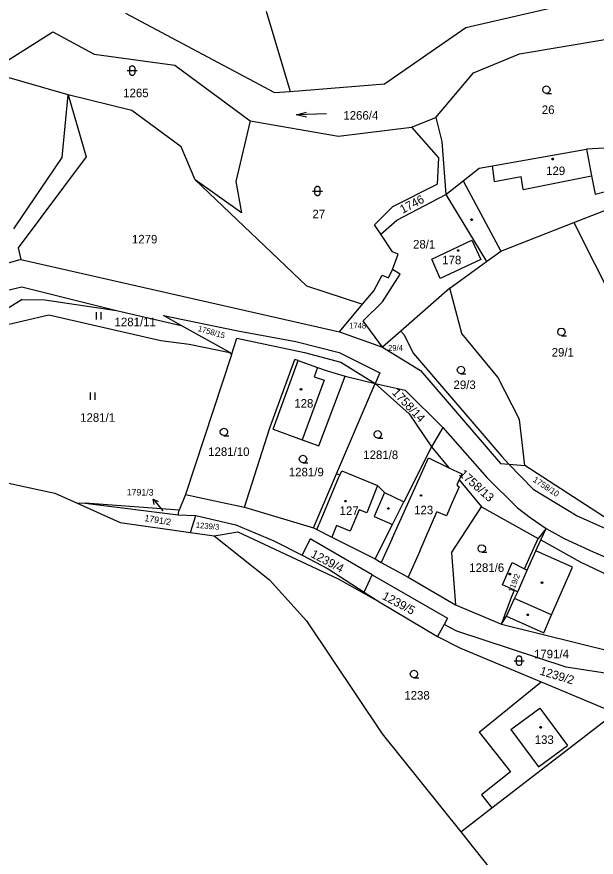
# Model space of a CAD drawing. Extents: x -799786 to -795190, y -1021716 to -1017834.
# Drawn here: x -798278.5 to -798163.2, y -1019191.9 to -1019024.7 of the extents above; entities that cross this region are included whole.
import ezdxf

# ---------------------------------------------------------------- set-up
doc = ezdxf.new("R2010")
doc.units = 0
for name, color, linetype in [('Default', 7, 'Continuous'), ('KN_HRANICE', 7, 'Continuous'), ('KN_KULTURY', 7, 'Continuous'), ('KN_PARCELY', 7, 'Continuous'), ('KN_SLUCKY', 7, 'Continuous')]:
    doc.layers.add(name, color=color, linetype=linetype)

# ---------------------------------------------------------------- blocks, each defined once
blk = doc.blocks.new('304')
at = {"layer": 'Default'}
blk.add_lwpolyline([(0, 0), (-0.38, 0.1), (-0.65, 0.37), (-0.75, 0.74), (-0.65, 1.11), (-0.38, 1.38), (-0.01, 1.48), (0.36, 1.38), (0.63, 1.11), (0.73, 0.73), (0.63, 0.35), (0.36, 0.08), (-0.02, -0.02), (0.98, -0.02)], dxfattribs=at)
blk = doc.blocks.new('306')
at = {"layer": 'Default'}
for p, q in [((-0.5, 1.5), (-0.5, 0)), ((0.5, 0), (0.5, 1.5))]:
    blk.add_line(p, q, dxfattribs=at)
blk = doc.blocks.new('316')
at = {"layer": 'Default'}
for points in [[(-0.5, 1.5), (-0.4, 1.79), (-0.15, 1.97), (0.16, 1.97), (0.41, 1.79), (0.51, 1.5), (0.51, 0.5), (0.41, 0.21), (0.16, 0.03), (-0.15, 0.03), (-0.4, 0.21), (-0.5, 0.5), (-0.5, 1.5)], [(-1, 1), (0.27, 1), (1, 1)]]:
    blk.add_lwpolyline(points, dxfattribs=at)
blk = doc.blocks.new('802')
at = {"layer": 'Default'}
blk.add_line((-3, 0), (3, 0), dxfattribs=at)
blk.add_lwpolyline([(1, 0.5), (3, 0), (1, -0.5)], dxfattribs=at)
blk = doc.blocks.new('10292')
at = {"layer": 'Default'}
blk.add_line((0, 3), (0, 0), dxfattribs=at)
blk.add_lwpolyline([(-0.5, 2), (0, 3), (0.5, 2)], dxfattribs=at)
blk = doc.blocks.new('402')
at = {"layer": 'Default'}
blk.add_lwpolyline([(0.09, 0.15), (0.18, 0), (0.09, -0.15), (-0.09, -0.15), (-0.18, 0), (-0.09, 0.15), (0.09, 0.15)], dxfattribs=at)

msp = doc.modelspace()

# ---------------------------------------------------------------- linework, layer by layer
at = {"layer": 'KN_HRANICE'}
for p, q in [((-798189.16, -1019026.83), (-798161.85, -1019020.48)), ((-798256.91, -1019023.98), (-798227.2, -1019039.74)), ((-798228.9, -1019023.55), (-798224.09, -1019039.53)), ((-798284.03, -1019035.68), (-798271.37, -1019027.66)), ((-798271.37, -1019027.66), (-798263.11, -1019032.14)), ((-798205.34, -1019038), (-798189.16, -1019026.83)), ((-798178.49, -1019032.04), (-798161.12, -1019029.12)), ((-798263.11, -1019032.14), (-798247.1, -1019034.33)), ((-798187.61, -1019035.85), (-798178.49, -1019032.04)), ((-798247.1, -1019034.33), (-798232.07, -1019045.38)), ((-798268.28, -1019040.2), (-798284.03, -1019035.68)), ((-798195.12, -1019044.71), (-798187.61, -1019035.85)), ((-798227.2, -1019039.74), (-798224.09, -1019039.53)), ((-798224.09, -1019039.53), (-798205.34, -1019038)), ((-798269.48, -1019052.64), (-798268.28, -1019040.2)), ((-798255.65, -1019043.29), (-798268.28, -1019040.2)), ((-798268.28, -1019040.2), (-798264.7, -1019052.54)), ((-798245.8, -1019050.55), (-798255.65, -1019043.29)), ((-798232.07, -1019045.38), (-798234.96, -1019057.42)), ((-798232.07, -1019045.38), (-798214.47, -1019048.4)), ((-798199.94, -1019046.65), (-798195.12, -1019044.71)), ((-798195.12, -1019044.71), (-798193.95, -1019049.51)), ((-798214.47, -1019048.4), (-798199.94, -1019046.65)), ((-798199.94, -1019046.65), (-798194.61, -1019052.72)), ((-798193.95, -1019049.51), (-798193.16, -1019060.03)), ((-798243.02, -1019057.12), (-798245.8, -1019050.55)), ((-798183.88, -1019054.32), (-798165.14, -1019051)), ((-798157.02, -1019050.59), (-798165.14, -1019051)), ((-798165.14, -1019051), (-798164.12, -1019056.34)), ((-798279.13, -1019066.87), (-798269.48, -1019052.64)), ((-798264.7, -1019052.54), (-798278.23, -1019070.65)), ((-798194.61, -1019052.72), (-798194.84, -1019057.97)), ((-798186.5, -1019054.79), (-798183.88, -1019054.32)), ((-798189.68, -1019057.3), (-798186.5, -1019054.79)), ((-798163.44, -1019059.94), (-798148.3, -1019056.22)), ((-798233.77, -1019063.69), (-798243.02, -1019057.12)), ((-798243.02, -1019057.12), (-798220.85, -1019078.22)), ((-798234.96, -1019057.42), (-798233.77, -1019063.69)), ((-798193.16, -1019060.03), (-798189.68, -1019057.3)), ((-798167.64, -1019065.62), (-798146.66, -1019057.36)), ((-798164.12, -1019056.34), (-798163.44, -1019059.94)), ((-798203.7, -1019062.43), (-798194.84, -1019057.97)), ((-798202.86, -1019065.12), (-798193.16, -1019060.03)), ((-798193.16, -1019060.03), (-798185.02, -1019073.35)), ((-798207.32, -1019066.09), (-798203.7, -1019062.43)), ((-798206.08, -1019067.93), (-798207.32, -1019066.09)), ((-798206.08, -1019067.93), (-798202.86, -1019065.12)), ((-798182.19, -1019071.31), (-798167.64, -1019065.62)), ((-798167.64, -1019065.62), (-798151.06, -1019098.77)), ((-798203.74, -1019071.47), (-798206.08, -1019067.93)), ((-798278.23, -1019070.65), (-798277.73, -1019072.94)), ((-798185.02, -1019073.35), (-798182.19, -1019071.31)), ((-798277.73, -1019072.94), (-798294.15, -1019077.72)), ((-798277.73, -1019072.94), (-798214.27, -1019087.39)), ((-798202.62, -1019071.89), (-798203.74, -1019071.47)), ((-798203.72, -1019074.94), (-798202.62, -1019071.89)), ((-798192.35, -1019078.65), (-798185.02, -1019073.35)), ((-798207.48, -1019079.22), (-798205.8, -1019076.09)), ((-798205.8, -1019076.09), (-798204.52, -1019076.62)), ((-798205.73, -1019081.39), (-798202.2, -1019075.87)), ((-798204.52, -1019076.62), (-798203.72, -1019074.94)), ((-798202.2, -1019075.87), (-798203.72, -1019074.94)), ((-798292.31, -1019081.83), (-798277.52, -1019078.42)), ((-798277.52, -1019078.42), (-798258.67, -1019083.12)), ((-798220.85, -1019078.22), (-798209.69, -1019081.83)), ((-798209.69, -1019081.83), (-798207.48, -1019079.22)), ((-798192.35, -1019078.65), (-798202.12, -1019087.23)), ((-798189.97, -1019087.69), (-798192.35, -1019078.65)), ((-798277.42, -1019080.9), (-798285.9, -1019086.17)), ((-798277.42, -1019080.9), (-798272.92, -1019080.98)), ((-798272.92, -1019080.98), (-798258.67, -1019083.12)), ((-798214.27, -1019087.39), (-798209.69, -1019081.83)), ((-798209.57, -1019085.19), (-798205.73, -1019081.39)), ((-798283.51, -1019086.63), (-798272.14, -1019083.99)), ((-798272.14, -1019083.99), (-798249.85, -1019089.07)), ((-798258.67, -1019083.12), (-798245.78, -1019086.08)), ((-798236.1, -1019091.47), (-798245.78, -1019086.08)), ((-798205.73, -1019090.39), (-798209.57, -1019085.19)), ((-798214.27, -1019087.39), (-798205.73, -1019090.39)), ((-798202.12, -1019087.23), (-798205.73, -1019090.39)), ((-798182.82, -1019096.35), (-798189.97, -1019087.69)), ((-798249.85, -1019089.07), (-798244.19, -1019089.84)), ((-798235.78, -1019091.93), (-798234.73, -1019088.61)), ((-798234.73, -1019088.61), (-798221.24, -1019091.45)), ((-798244.19, -1019089.84), (-798236.1, -1019091.47)), ((-798205.73, -1019090.39), (-798198.18, -1019095.03)), ((-798235.78, -1019091.93), (-798244.94, -1019119.72)), ((-798236.1, -1019091.47), (-798235.78, -1019091.93)), ((-798228.16, -1019106.48), (-798223.16, -1019092.85)), ((-798222.5, -1019093.08), (-798223.16, -1019092.85)), ((-798221.24, -1019091.45), (-798214.02, -1019093.39)), ((-798227.51, -1019106.73), (-798222.5, -1019093.08)), ((-798222.5, -1019093.08), (-798218.69, -1019094.45)), ((-798218.69, -1019094.45), (-798216.78, -1019095.14)), ((-798214.02, -1019093.39), (-798207.19, -1019097.64)), ((-798218.4, -1019110.04), (-798213.18, -1019096.15)), ((-798216.78, -1019095.14), (-798213.18, -1019096.15)), ((-798213.18, -1019096.15), (-798207.19, -1019097.64)), ((-798198.18, -1019095.03), (-798182.29, -1019113.53)), ((-798178.45, -1019104.78), (-798182.82, -1019096.35)), ((-798214.89, -1019115.61), (-798207.19, -1019097.64)), ((-798207.19, -1019097.64), (-798200.43, -1019103.69)), ((-798200.43, -1019103.69), (-798195.98, -1019110.26)), ((-798193.73, -1019106.42), (-798195.98, -1019110.26)), ((-798177.44, -1019113.97), (-798178.45, -1019104.78)), ((-798233.18, -1019122.25), (-798228.16, -1019106.48)), ((-798227.51, -1019106.73), (-798221.72, -1019108.83)), ((-798221.72, -1019108.83), (-798218.4, -1019110.04)), ((-798195.98, -1019110.26), (-798201.47, -1019121.22)), ((-798195.98, -1019110.26), (-798192.54, -1019114.39)), ((-798182.29, -1019113.53), (-798180.57, -1019113.69)), ((-798180.57, -1019113.69), (-798177.44, -1019113.97)), ((-798158.15, -1019126.49), (-798177.44, -1019113.97)), ((-798219.5, -1019126.38), (-798214.89, -1019115.61)), ((-798214.24, -1019115.88), (-798214.89, -1019115.61)), ((-798281.71, -1019117.15), (-798270.95, -1019119.48)), ((-798206.71, -1019117.93), (-798205.33, -1019119.33)), ((-798190.5, -1019116.82), (-798186.04, -1019122.17)), ((-798270.95, -1019119.48), (-798266.63, -1019121.42)), ((-798244.94, -1019119.72), (-798246.22, -1019122.85)), ((-798244.94, -1019119.72), (-798237.56, -1019121.31)), ((-798205.33, -1019119.33), (-798201.47, -1019121.22)), ((-798266.63, -1019121.42), (-798257.97, -1019125.3)), ((-798266.63, -1019121.42), (-798264.91, -1019121.48)), ((-798246.22, -1019122.85), (-798264.91, -1019121.48)), ((-798264.91, -1019121.48), (-798246.43, -1019123.75)), ((-798237.56, -1019121.31), (-798233.18, -1019122.25)), ((-798203.76, -1019125.7), (-798201.47, -1019121.22)), ((-798246.43, -1019123.75), (-798246.22, -1019122.85)), ((-798233.18, -1019122.25), (-798219.5, -1019126.38)), ((-798192, -1019131.32), (-798186.04, -1019122.17)), ((-798186.04, -1019122.17), (-798174.76, -1019128.46)), ((-798246.43, -1019123.75), (-798242.91, -1019123.9)), ((-798243.97, -1019127.3), (-798242.91, -1019123.9)), ((-798242.91, -1019123.9), (-798234.96, -1019125.77)), ((-798257.97, -1019125.3), (-798243.97, -1019127.3)), ((-798234.96, -1019125.77), (-798227.36, -1019128.96)), ((-798219.5, -1019126.38), (-798218.83, -1019126.71)), ((-798207.23, -1019132.5), (-798203.76, -1019125.7)), ((-798173.18, -1019126.48), (-798174.76, -1019128.46)), ((-798174.26, -1019128.74), (-798173.18, -1019126.48)), ((-798243.97, -1019127.3), (-798239.23, -1019127.98)), ((-798239.23, -1019127.98), (-798234.52, -1019127.16)), ((-798239.23, -1019127.98), (-798228.23, -1019136.68)), ((-798234.52, -1019127.16), (-798214.54, -1019136.48)), ((-798218.83, -1019126.71), (-798215.85, -1019128.2)), ((-798227.36, -1019128.96), (-798221.75, -1019131.83)), ((-798220.12, -1019128.55), (-798221.75, -1019131.83)), ((-798207.8, -1019135.71), (-798220.12, -1019128.55)), ((-798215.85, -1019128.2), (-798207.23, -1019132.5)), ((-798175.73, -1019130.68), (-798174.76, -1019128.46)), ((-798175.25, -1019130.94), (-798174.26, -1019128.74)), ((-798174.26, -1019128.74), (-798166.41, -1019133.11)), ((-798192, -1019131.32), (-798191.24, -1019141.68)), ((-798177.5, -1019134.51), (-798175.73, -1019130.68)), ((-798176.95, -1019134.79), (-798175.25, -1019130.94)), ((-798207.23, -1019132.5), (-798205.98, -1019133.26)), ((-798166.41, -1019133.11), (-798156.68, -1019137.76)), ((-798205.98, -1019133.26), (-798200.63, -1019136.21)), ((-798178.84, -1019139.07), (-798176.95, -1019134.79)), ((-798214.54, -1019136.48), (-798206.29, -1019141.16)), ((-798209.36, -1019139.14), (-798207.8, -1019135.71)), ((-798200.63, -1019136.21), (-798191.24, -1019141.68)), ((-798228.23, -1019136.68), (-798220.84, -1019144.84)), ((-798209.36, -1019139.14), (-798206.29, -1019141.16)), ((-798180.1, -1019140.15), (-798179.47, -1019138.79)), ((-798179.48, -1019140.44), (-798178.84, -1019139.07)), ((-798206.29, -1019141.16), (-798194.81, -1019147.97)), ((-798182.05, -1019145.56), (-798180.1, -1019140.15)), ((-798181.07, -1019143.95), (-798179.48, -1019140.44)), ((-798191.24, -1019141.68), (-798182.05, -1019145.56)), ((-798220.84, -1019144.84), (-798205.83, -1019167.34)), ((-798182.05, -1019145.56), (-798181.07, -1019143.95)), ((-798193.49, -1019145.63), (-798194.81, -1019147.97)), ((-798190.98, -1019146.92), (-798193.49, -1019145.63)), ((-798182.05, -1019145.56), (-798139.27, -1019156.11)), ((-798194.81, -1019147.97), (-798190.22, -1019150.28)), ((-798169.21, -1019154.08), (-798190.98, -1019146.92)), ((-798190.22, -1019150.28), (-798174.14, -1019157.02)), ((-798140.66, -1019158.48), (-798169.21, -1019154.08)), ((-798186.49, -1019167.03), (-798174.14, -1019157.02)), ((-798174.14, -1019157.02), (-798159.42, -1019163.19)), ((-798183.97, -1019182.09), (-798159.42, -1019163.19)), ((-798205.83, -1019167.34), (-798190.13, -1019186.83)), ((-798186.49, -1019167.03), (-798180.26, -1019174.89)), ((-798180.26, -1019174.89), (-798186.02, -1019179.49)), ((-798186.02, -1019179.49), (-798183.97, -1019182.09)), ((-798190.13, -1019186.83), (-798183.97, -1019182.09)), ((-798190.13, -1019186.83), (-798182.57, -1019196.42))]:
    msp.add_line(p, q, dxfattribs=at)
msp.add_lwpolyline([(-798195.91, -1019072.93), (-798187.93, -1019069.13), (-798186.15, -1019073), (-798194.26, -1019076.74)], close=True, dxfattribs=at)
for points in [[(-798245.78, -1019086.08), (-798249.3, -1019084.11), (-798234.55, -1019087.18), (-798222.98, -1019089.3), (-798214.38, -1019091.46), (-798206.26, -1019095.51), (-798207.19, -1019097.64)], [(-798202.12, -1019087.23), (-798201.5, -1019087.88), (-798199.54, -1019091.67), (-798182.01, -1019112.18), (-798180.57, -1019113.69)], [(-798207.19, -1019097.64), (-798201.21, -1019098.97), (-798193.73, -1019106.42)], [(-798193.73, -1019106.42), (-798184.98, -1019116.32), (-798178.89, -1019122.36), (-798176.36, -1019124.29), (-798173.18, -1019126.48)], [(-798192.54, -1019114.39), (-798189.93, -1019115.64), (-798190.5, -1019116.82)], [(-798180.57, -1019113.69), (-798175.77, -1019118.66), (-798166.98, -1019124), (-798161.34, -1019126.51), (-798158.43, -1019127.29), (-798158.15, -1019126.49)], [(-798214.24, -1019115.88), (-798213.86, -1019115), (-798206.71, -1019117.93)], [(-798173.18, -1019126.48), (-798169.57, -1019128.51), (-798163.84, -1019131.17), (-798156.24, -1019134.41), (-798147.55, -1019137.5), (-798137.22, -1019139.95), (-798137.74, -1019143.13)], [(-798221.75, -1019131.83), (-798216.55, -1019134.49), (-798209.36, -1019139.14)], [(-798179.47, -1019138.79), (-798181.88, -1019137.71), (-798179.91, -1019133.27), (-798177.5, -1019134.51)], [(-798207.8, -1019135.71), (-798192.78, -1019144.36), (-798193.49, -1019145.63)]]:
    msp.add_lwpolyline(points, dxfattribs=at)
at = {"layer": 'KN_SLUCKY'}
for p, q in [((-798183.46, -1019057.46), (-798183.88, -1019054.32)), ((-798189.68, -1019057.3), (-798182.19, -1019071.31)), ((-798183.46, -1019057.46), (-798178.16, -1019056.45)), ((-798177.78, -1019059.04), (-798178.16, -1019056.45)), ((-798177.78, -1019059.04), (-798164.12, -1019056.34)), ((-798218.69, -1019094.45), (-798219.34, -1019096.34)), ((-798219.34, -1019096.34), (-798217.34, -1019096.99)), ((-798217.34, -1019096.99), (-798221.72, -1019108.83)), ((-798203.83, -1019128.48), (-798197.73, -1019114.97)), ((-798191.85, -1019121.33), (-798193.02, -1019123.97)), ((-798198.34, -1019130.99), (-798194.9, -1019123.15)), ((-798193.02, -1019123.97), (-798194.9, -1019123.15)), ((-798218.83, -1019126.71), (-798217.94, -1019124.72)), ((-798214.91, -1019125.93), (-798215.85, -1019128.2)), ((-798212.17, -1019127.02), (-798214.91, -1019125.93)), ((-798203.83, -1019128.48), (-798205.98, -1019133.26)), ((-798198.34, -1019130.99), (-798200.63, -1019136.21)), ((-798167.92, -1019134.21), (-798175.25, -1019130.94)), ((-798177.5, -1019134.51), (-798176.95, -1019134.79)), ((-798172.11, -1019143.69), (-798167.92, -1019134.21)), ((-798179.47, -1019138.79), (-798178.84, -1019139.07)), ((-798172.11, -1019143.69), (-798179.48, -1019140.44)), ((-798180.17, -1019166.51), (-798174.4, -1019162.26)), ((-798174.4, -1019162.26), (-798168.9, -1019169.7)), ((-798180.17, -1019166.51), (-798174.67, -1019173.95)), ((-798174.67, -1019173.95), (-798168.9, -1019169.7))]:
    msp.add_line(p, q, dxfattribs=at)
for points in [[(-798197.73, -1019114.97), (-798196.59, -1019112.44), (-798192.54, -1019114.39)], [(-798217.94, -1019124.72), (-798214.47, -1019116.41), (-798214.24, -1019115.88)], [(-798206.71, -1019117.93), (-798208.86, -1019123.41), (-798210.4, -1019122.79), (-798212.17, -1019127.02)], [(-798190.5, -1019116.82), (-798190.98, -1019117.82), (-798190.78, -1019118.07), (-798190.47, -1019118.22), (-798191.85, -1019121.33)], [(-798205.33, -1019119.33), (-798207.39, -1019124.11), (-798203.76, -1019125.7)], [(-798181.07, -1019143.95), (-798173.64, -1019147.25), (-798172.11, -1019143.69)]]:
    msp.add_lwpolyline(points, dxfattribs=at)

# ---------------------------------------------------------------- block references
at = {"layer": 'KN_KULTURY'}
for name, p in [('316', (-798255.55, -1019036.37)), ('304', (-798173.11, -1019039.91)), ('402', (-798171.86, -1019052.97)), ('316', (-798218.69, -1019060.34)), ('402', (-798188.01, -1019065.04)), ('402', (-798190.69, -1019071.19)), ('306', (-798262.23, -1019084.93)), ('304', (-798170.13, -1019088.11)), ('304', (-798190.12, -1019095.69)), ('306', (-798263.42, -1019100.9)), ('402', (-798221.97, -1019098.8)), ('304', (-798237.3, -1019108.02)), ('304', (-798206.67, -1019108.5)), ('304', (-798221.56, -1019113.41)), ('402', (-798198.09, -1019119.93)), ('402', (-798213.11, -1019121.07)), ('402', (-798204.59, -1019122.53)), ('304', (-798185.97, -1019131.21)), ('402', (-798174.01, -1019137.26)), ('402', (-798176.83, -1019143.66)), ('316', (-798178.56, -1019153.8)), ('304', (-798199.48, -1019156.18)), ('402', (-798174.26, -1019166.05))]:
    msp.add_blockref(name, p, dxfattribs=at)
for name, p, rotation in [('802', (-798219.87, -1019044.09), -178.37237900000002), ('402', (-798180.41, -1019135.56), -11.92813899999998)]:
    msp.add_blockref(name, p, dxfattribs=dict(at, rotation=rotation))
at = {"layer": 'KN_PARCELY', "rotation": 39.992453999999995}
msp.add_blockref('10292', (-798249.48, -1019122.95), dxfattribs=at)

# ---------------------------------------------------------------- texts
at = {"layer": 'KN_PARCELY'}
for s, height, p in [('1265', 1.7, (-798257.34, -1019040.67)), ('26', 1.7, (-798174.04, -1019044.02)), ('1266/4', 1.7, (-798213.53, -1019045.14)), ('129', 1.7, (-798173.18, -1019056.17)), ('27', 1.7, (-798219.68, -1019064.77)), ('1279', 1.7, (-798255.6, -1019069.77)), ('28/1', 1.7, (-798199.66, -1019070.78)), ('178', 1.7, (-798193.85, -1019073.92)), ('1281/11', 1.7, (-798259.06, -1019086.24)), ('1748', 1.14, (-798212.38, -1019086.69)), ('29/1', 1.7, (-798172.07, -1019092.28)), ('29/3', 1.7, (-798191.61, -1019098.75)), ('128', 1.7, (-798223.29, -1019102.44)), ('1281/1', 1.7, (-798265.91, -1019105.26)), ('1281/10', 1.7, (-798240.43, -1019112.06)), ('1281/8', 1.7, (-798209.57, -1019112.68)), ('1281/9', 1.7, (-798224.38, -1019116.11)), ('1791/3', 0.1, (-798249.78, -1019122.95)), ('127', 1.7, (-798214.28, -1019123.8)), ('123', 1.7, (-798199.44, -1019123.66)), ('1281/6', 1.7, (-798188.47, -1019135.14)), ('1791/4', 1.7, (-798175.59, -1019152.32)), ('1238', 1.7, (-798201.4, -1019160.54)), ('133', 1.7, (-798175.45, -1019169.36))]:
    msp.add_text(s, height=height, dxfattribs=at).set_placement(p)
for s, height, rotation, p in [('1746', 1.7, 27.846, (-798201.73, -1019063.88)), ('1758/15', 1.14, 344.061, (-798242.57, -1019087.19)), ('29/4', 1.14, 0.115, (-798204.64, -1019091.12)), ('1758/14', 1.7, 313.465, (-798203.96, -1019099.57)), ('1758/13', 1.7, 318.221, (-798190.63, -1019115.84)), ('1758/10', 1.2, 326.529, (-798175.92, -1019117.08)), ('1791/3', 1.3, 359.588, (-798256.63, -1019119.91)), ('1791/2', 1.3, 350.421, (-798253.18, -1019125.01)), ('1239/3', 1.14, 354.833, (-798242.92, -1019126.36)), ('1239/4', 1.7, 331.972, (-798220.16, -1019132.09)), ('119/2', 1.14, 68.64, (-798179.72, -1019139.33)), ('1239/5', 1.7, 331.857, (-798205.97, -1019140.44)), ('1239/2', 1.7, 343.259, (-798174.57, -1019155.54))]:
    msp.add_text(s, height=height, rotation=rotation, dxfattribs=at).set_placement(p)

doc.saveas('drawing.dxf')
